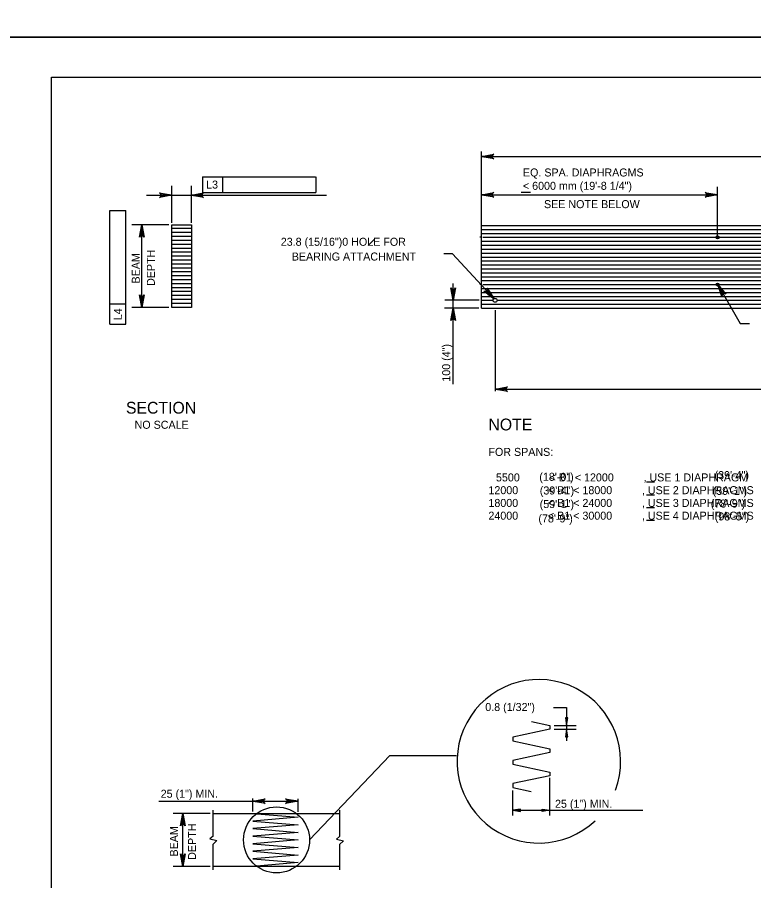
# Model space of a CAD drawing. Extents: x 638263 to 640360, y 293683 to 298655.
# Drawn here: x 639303.6 to 639579.7, y 296931.3 to 297255 of the extents above; entities that cross this region are included whole.
import ezdxf

# ---------------------------------------------------------------- set-up
doc = ezdxf.new("R2010")
doc.units = 0
for name, color, linetype in [('2', 7, 'Continuous'), ('4', 7, 'Continuous'), ('5', 7, 'Continuous'), ('6', 7, 'Continuous'), ('7', 7, 'Continuous'), ('8', 7, 'Continuous'), ('PLT-BNDY', 7, 'Continuous')]:
    doc.layers.add(name, color=color, linetype=linetype)

msp = doc.modelspace()

# ---------------------------------------------------------------- linework, layer by layer
at = {"layer": '2'}
for p, q in [((639316.46, 296668.46), (639316.46, 297232.46)), ((639316.46, 297232.46), (640102.46, 297232.46)), ((639361.52, 297146.18), (639361.52, 297177.19)), ((639361.52, 297177.19), (639368.9, 297177.19)), ((639368.9, 297177.19), (639368.9, 297146.18)), ((639477.54, 297145.89), (639477.54, 297176.89)), ((639477.54, 297176.89), (639831.87, 297176.89)), ((639368.9, 297146.18), (639361.52, 297146.18)), ((639477.54, 297145.89), (639831.87, 297145.89))]:
    msp.add_line(p, q, dxfattribs=at)
at = {"layer": '4'}
for centre, radius in [((639566.13, 297172.46), 0.554), ((639566.13, 297154.75), 0.554), ((639482.71, 297148.84), 0.738)]:
    msp.add_circle(centre, radius, dxfattribs=at)
at = {"layer": '5'}
for p, q in [((639477.54, 297177.6), (639477.54, 297204.59)), ((639477.54, 297202.73), (639831.87, 297202.73)), ((639372.96, 297195.19), (639372.96, 297189.28)), ((639372.96, 297195.19), (639380.52, 297195.19)), ((639380.52, 297195.19), (639380.52, 297189.28)), ((639380.52, 297195.19), (639415.32, 297195.19)), ((639415.48, 297195.19), (639415.48, 297189.28)), ((639361.52, 297177.92), (639361.52, 297191.75)), ((639368.9, 297177.92), (639368.9, 297191.75)), ((639477.54, 297173.02), (639477.54, 297191.37)), ((639566.12, 297173.02), (639566.12, 297191.37)), ((639352.01, 297188.26), (639419.47, 297188.26)), ((639372.96, 297189.28), (639415.48, 297189.28)), ((639477.54, 297188.4), (639566.12, 297188.4)), ((639492.44, 297189.39), (639495.95, 297189.39)), ((639338.31, 297182.46), (639344.22, 297182.46)), ((639338.31, 297147.5), (639338.31, 297182.46)), ((639344.22, 297139.94), (639344.22, 297182.46)), ((639360.4, 297177.19), (639346.58, 297177.19)), ((639350.24, 297146.18), (639350.24, 297177.19)), ((639437.51, 297171.75), (639435.11, 297169.35)), ((639484.39, 297172.46), (639857.82, 297172.46)), ((639466.7, 297166.24), (639463.51, 297166.24)), ((639482.29, 297149.45), (639466.7, 297166.24)), ((639466.95, 297117.39), (639466.95, 297155.16)), ((639484.39, 297154.75), (639872.19, 297154.75)), ((639566.14, 297154.75), (639574.58, 297140.14)), ((639476.67, 297148.84), (639463.85, 297148.84)), ((639338.31, 297139.94), (639338.31, 297147.5)), ((639338.31, 297147.5), (639344.22, 297147.5)), ((639360.4, 297146.18), (639346.58, 297146.18)), ((639476.59, 297145.89), (639463.78, 297145.89)), ((639482.71, 297145.15), (639482.71, 297114.8)), ((639338.31, 297139.94), (639344.22, 297139.94)), ((639574.58, 297140.14), (639578.07, 297140.14)), ((639482.71, 297115.54), (639826.71, 297115.54)), ((639542.51, 297080.64), (639539.41, 297080.64)), ((639542.5, 297075.85), (639539.41, 297075.85)), ((639542.5, 297071.06), (639539.4, 297071.06)), ((639542.49, 297066.31), (639539.4, 297066.31)), ((639504.62, 296996.24), (639509.51, 296996.24)), ((639509.51, 296996.24), (639509.51, 296983.76)), ((639504.9, 296989.45), (639513.11, 296989.45)), ((639504.9, 296988.03), (639513.11, 296988.03)), ((639503.2, 296955.72), (639503.2, 296969.8)), ((639489.38, 296955.72), (639489.38, 296965.14)), ((639356.59, 296961.12), (639408.84, 296961.12)), ((639391.83, 296957.25), (639391.83, 296962.09)), ((639408.84, 296957.1), (639408.84, 296962.01)), ((639376.95, 296947.94), (639376.95, 296957.74)), ((639424.43, 296957.74), (639424.43, 296947.88)), ((639489.38, 296957.65), (639538.02, 296957.65)), ((639375.83, 296956.47), (639362.02, 296956.47)), ((639365.67, 296936.63), (639365.67, 296956.47)), ((639376.95, 296947.94), (639375.81, 296946.95)), ((639424.43, 296947.88), (639423.29, 296946.89)), ((639375.81, 296946.95), (639378.41, 296946.28)), ((639378.41, 296946.28), (639376.95, 296944.93)), ((639376.95, 296935.37), (639376.95, 296944.93)), ((639423.29, 296946.89), (639425.89, 296946.22)), ((639425.89, 296946.22), (639424.43, 296944.87)), ((639424.43, 296944.87), (639424.43, 296935.37)), ((639375.83, 296936.63), (639362.02, 296936.63))]:
    msp.add_line(p, q, dxfattribs=at)
for points in [[(639477.54, 297202.73), (639482.2, 297203.6), (639481.85, 297203.35), (639481.66, 297203.04), (639481.61, 297202.73), (639481.66, 297202.42), (639481.85, 297202.1), (639482.2, 297201.86), (639477.54, 297202.73), (639481.85, 297202.1), (639481.66, 297202.42), (639477.54, 297202.73), (639481.61, 297202.73), (639481.66, 297203.04), (639477.54, 297202.73), (639481.85, 297203.35)], [(639361.52, 297188.26), (639356.86, 297187.39), (639357.22, 297187.63), (639357.4, 297187.95), (639357.46, 297188.26), (639357.4, 297188.57), (639357.22, 297188.88), (639356.86, 297189.13), (639361.52, 297188.26), (639357.22, 297188.88), (639357.4, 297188.57), (639361.52, 297188.26), (639357.46, 297188.26), (639357.4, 297187.95), (639361.52, 297188.26), (639357.22, 297187.63)], [(639368.72, 297188.26), (639373.38, 297189.13), (639373.02, 297188.88), (639372.84, 297188.57), (639372.78, 297188.26), (639372.84, 297187.95), (639373.02, 297187.63), (639373.38, 297187.39), (639368.72, 297188.26), (639373.02, 297187.63), (639372.84, 297187.95), (639368.72, 297188.26), (639372.78, 297188.26), (639372.84, 297188.57), (639368.72, 297188.26), (639373.02, 297188.88)], [(639477.54, 297188.4), (639482.2, 297189.28), (639481.85, 297189.03), (639481.66, 297188.72), (639481.61, 297188.4), (639481.66, 297188.09), (639481.85, 297187.78), (639482.2, 297187.53), (639477.54, 297188.4), (639481.85, 297187.78), (639481.66, 297188.09), (639477.54, 297188.4), (639481.61, 297188.4), (639481.66, 297188.72), (639477.54, 297188.4), (639481.85, 297189.03)], [(639566.12, 297188.4), (639561.46, 297187.53), (639561.82, 297187.78), (639562.01, 297188.09), (639562.06, 297188.4), (639562.01, 297188.72), (639561.82, 297189.03), (639561.46, 297189.28), (639566.12, 297188.4), (639561.82, 297189.03), (639562.01, 297188.72), (639566.12, 297188.4), (639562.06, 297188.4), (639562.01, 297188.09), (639566.12, 297188.4), (639561.82, 297187.78)], [(639350.24, 297177.19), (639351.11, 297172.52), (639350.86, 297172.88), (639350.55, 297173.07), (639350.24, 297173.12), (639349.93, 297173.07), (639349.61, 297172.88), (639349.37, 297172.52), (639350.24, 297177.19), (639349.61, 297172.88), (639349.93, 297173.07), (639350.24, 297177.19), (639350.24, 297173.12), (639350.55, 297173.07), (639350.24, 297177.19), (639350.86, 297172.88)], [(639466.95, 297148.84), (639466.08, 297153.5), (639466.33, 297153.14), (639466.64, 297152.96), (639466.95, 297152.9), (639467.27, 297152.96), (639467.58, 297153.14), (639467.83, 297153.5), (639466.95, 297148.84), (639467.58, 297153.14), (639467.27, 297152.96), (639466.95, 297148.84), (639466.95, 297152.9), (639466.64, 297152.96), (639466.95, 297148.84), (639466.33, 297153.14)], [(639482.29, 297149.45), (639478.48, 297152.27), (639478.91, 297152.18), (639479.26, 297152.25), (639479.53, 297152.43), (639479.72, 297152.68), (639479.82, 297153.03), (639479.76, 297153.46), (639482.29, 297149.45), (639479.82, 297153.03), (639479.72, 297152.68), (639482.29, 297149.45), (639479.53, 297152.43), (639479.26, 297152.25), (639482.29, 297149.45), (639478.91, 297152.18)], [(639566.14, 297154.75), (639569.23, 297151.15), (639568.83, 297151.34), (639568.47, 297151.34), (639568.17, 297151.23), (639567.93, 297151.03), (639567.75, 297150.71), (639567.72, 297150.27), (639566.14, 297154.75), (639567.75, 297150.71), (639567.93, 297151.03), (639566.14, 297154.75), (639568.17, 297151.23), (639568.47, 297151.34), (639566.14, 297154.75), (639568.83, 297151.34)], [(639350.24, 297146.18), (639349.37, 297150.84), (639349.61, 297150.48), (639349.93, 297150.3), (639350.24, 297150.24), (639350.55, 297150.3), (639350.86, 297150.48), (639351.11, 297150.84), (639350.24, 297146.18), (639350.86, 297150.48), (639350.55, 297150.3), (639350.24, 297146.18), (639350.24, 297150.24), (639349.93, 297150.3), (639350.24, 297146.18), (639349.61, 297150.48)], [(639466.95, 297145.89), (639467.82, 297141.23), (639467.57, 297141.59), (639467.26, 297141.77), (639466.95, 297141.83), (639466.63, 297141.77), (639466.32, 297141.59), (639466.07, 297141.23), (639466.95, 297145.89), (639466.32, 297141.59), (639466.63, 297141.77), (639466.95, 297145.89), (639466.95, 297141.83), (639467.26, 297141.77), (639466.95, 297145.89), (639467.57, 297141.59)], [(639482.71, 297115.54), (639487.37, 297116.41), (639487.01, 297116.16), (639486.83, 297115.85), (639486.77, 297115.54), (639486.83, 297115.23), (639487.01, 297114.91), (639487.37, 297114.67), (639482.71, 297115.54), (639487.01, 297114.91), (639486.83, 297115.23), (639482.71, 297115.54), (639486.77, 297115.54), (639486.83, 297115.85), (639482.71, 297115.54), (639487.01, 297116.16)], [(639391.83, 296961.12), (639396.49, 296961.99), (639396.13, 296961.75), (639395.95, 296961.43), (639395.89, 296961.12), (639395.95, 296960.81), (639396.13, 296960.5), (639396.49, 296960.25), (639391.83, 296961.12), (639396.13, 296960.5), (639395.95, 296960.81), (639391.83, 296961.12), (639395.89, 296961.12), (639395.95, 296961.43), (639391.83, 296961.12), (639396.13, 296961.75)], [(639408.84, 296961.12), (639404.18, 296960.25), (639404.54, 296960.5), (639404.72, 296960.81), (639404.78, 296961.12), (639404.72, 296961.43), (639404.54, 296961.75), (639404.18, 296961.99), (639408.84, 296961.12), (639404.54, 296961.75), (639404.72, 296961.43), (639408.84, 296961.12), (639404.78, 296961.12), (639404.72, 296960.81), (639408.84, 296961.12), (639404.54, 296960.5)], [(639365.67, 296956.47), (639366.54, 296951.81), (639366.29, 296952.17), (639365.98, 296952.36), (639365.67, 296952.41), (639365.36, 296952.36), (639365.04, 296952.17), (639364.8, 296951.81), (639365.67, 296956.47), (639365.04, 296952.17), (639365.36, 296952.36), (639365.67, 296956.47), (639365.67, 296952.41), (639365.98, 296952.36), (639365.67, 296956.47), (639366.29, 296952.17)], [(639365.67, 296936.63), (639364.8, 296941.29), (639365.04, 296940.93), (639365.36, 296940.75), (639365.67, 296940.69), (639365.98, 296940.75), (639366.29, 296940.93), (639366.54, 296941.29), (639365.67, 296936.63), (639366.29, 296940.93), (639365.98, 296940.75), (639365.67, 296936.63), (639365.67, 296940.69), (639365.36, 296940.75), (639365.67, 296936.63), (639365.04, 296940.93)]]:
    msp.add_lwpolyline(points, dxfattribs=at)
for points in [[(639480.71, 297151.85), (639480.02, 297151.21), (639482.29, 297149.45)], [(639509.98, 296992.29), (639509.03, 296992.29), (639509.51, 296989.45)], [(639509.03, 296985.2), (639509.98, 296985.2), (639509.51, 296988.03)], [(639492.22, 296957.18), (639492.22, 296958.13), (639489.38, 296957.65)], [(639500.37, 296957.18), (639500.37, 296958.13), (639503.2, 296957.65)]]:
    msp.add_lwpolyline(points, close=True, dxfattribs=at)
at = {"layer": '6'}
for p, q in [((639368.9, 297175.71), (639361.52, 297175.71)), ((639368.9, 297174.23), (639361.52, 297174.23)), ((639477.54, 297175.42), (639831.87, 297175.42)), ((639368.9, 297172.76), (639361.52, 297172.76)), ((639368.9, 297171.28), (639361.52, 297171.28)), ((639477.54, 297172.46), (639476.99, 297172.46)), ((639477.54, 297173.94), (639831.87, 297173.94)), ((639477.54, 297170.99), (639831.87, 297170.99)), ((639478.1, 297172.46), (639565.57, 297172.46)), ((639566.68, 297172.46), (639654.15, 297172.46)), ((639368.9, 297169.8), (639361.52, 297169.8)), ((639368.9, 297168.33), (639361.52, 297168.33)), ((639477.54, 297169.51), (639831.87, 297169.51)), ((639477.54, 297168.04), (639831.87, 297168.04)), ((639368.9, 297166.85), (639361.52, 297166.85)), ((639368.9, 297165.37), (639361.52, 297165.37)), ((639477.54, 297166.56), (639831.87, 297166.56)), ((639477.54, 297165.08), (639831.87, 297165.08)), ((639368.9, 297163.9), (639361.52, 297163.9)), ((639368.9, 297162.42), (639361.52, 297162.42)), ((639477.54, 297163.61), (639831.87, 297163.61)), ((639477.54, 297162.13), (639831.87, 297162.13)), ((639368.9, 297160.94), (639361.52, 297160.94)), ((639368.9, 297159.47), (639361.52, 297159.47)), ((639477.54, 297160.65), (639831.87, 297160.65)), ((639477.54, 297159.18), (639831.87, 297159.18)), ((639368.9, 297157.99), (639361.52, 297157.99)), ((639368.9, 297156.51), (639361.52, 297156.51)), ((639368.9, 297155.04), (639361.52, 297155.04)), ((639477.54, 297157.7), (639831.87, 297157.7)), ((639477.54, 297156.22), (639831.87, 297156.22)), ((639368.9, 297153.56), (639361.52, 297153.56)), ((639368.9, 297152.09), (639361.52, 297152.09)), ((639477.54, 297154.75), (639476.99, 297154.75)), ((639477.54, 297153.27), (639831.87, 297153.27)), ((639477.54, 297151.79), (639831.87, 297151.79)), ((639478.1, 297154.75), (639565.57, 297154.75)), ((639566.68, 297154.75), (639654.15, 297154.75)), ((639368.9, 297150.61), (639361.52, 297150.61)), ((639368.9, 297149.13), (639361.52, 297149.13)), ((639477.54, 297150.32), (639831.87, 297150.32)), ((639477.54, 297148.84), (639481.97, 297148.84)), ((639483.45, 297148.84), (639825.97, 297148.84)), ((639368.9, 297147.66), (639361.52, 297147.66)), ((639477.54, 297147.36), (639831.87, 297147.36))]:
    msp.add_line(p, q, dxfattribs=at)
at = {"layer": '7'}
for p, q in [((639496.29, 296990.92), (639503.2, 296989.45)), ((639503.2, 296988.03), (639489.38, 296985.1)), ((639503.2, 296989.45), (639503.2, 296988.03)), ((639489.38, 296985.1), (639489.38, 296983.68)), ((639489.38, 296983.68), (639503.2, 296980.74)), ((639503.2, 296980.74), (639503.2, 296979.33)), ((639503.2, 296979.33), (639489.34, 296976.38)), ((639489.34, 296976.38), (639489.34, 296974.96)), ((639489.34, 296974.96), (639503.2, 296972.01)), ((639503.2, 296970.6), (639489.34, 296967.65)), ((639503.2, 296972.01), (639503.2, 296970.6)), ((639489.34, 296967.65), (639489.34, 296966.23)), ((639489.34, 296966.23), (639496.27, 296964.76)), ((639376.95, 296956.47), (639424.43, 296956.47)), ((639391.83, 296956.47), (639408.84, 296955.06)), ((639408.84, 296955.06), (639391.83, 296953.64)), ((639391.83, 296953.64), (639408.84, 296952.22)), ((639408.84, 296952.22), (639391.83, 296950.8)), ((639391.83, 296950.8), (639408.84, 296949.39)), ((639408.84, 296949.39), (639391.83, 296947.97)), ((639391.83, 296947.97), (639408.84, 296946.55)), ((639408.84, 296946.55), (639391.83, 296945.13)), ((639391.83, 296945.13), (639408.84, 296943.72)), ((639408.84, 296943.72), (639391.83, 296942.3)), ((639391.83, 296942.3), (639408.84, 296940.88)), ((639408.84, 296940.88), (639391.83, 296939.47)), ((639391.83, 296939.47), (639408.84, 296938.05)), ((639408.84, 296938.05), (639391.83, 296936.63)), ((639424.43, 296936.63), (639376.95, 296936.63))]:
    msp.add_line(p, q, dxfattribs=at)
at = {"layer": '8'}
for p, q in [((639413.15, 296946.55), (639443.3, 296978.17)), ((639443.3, 296978.17), (639468.22, 296978.17))]:
    msp.add_line(p, q, dxfattribs=at)
msp.add_circle((639400.78, 296946.55), 12.37, dxfattribs=at)
msp.add_arc((639499.09, 296976.03), 30.66, 339.3834, 313.4181, dxfattribs=at)
at = {"layer": 'PLT-BNDY'}
for points in [[(639276.46, 297841.46), (640117.46, 297841.46), (640117.46, 297247.46), (639276.46, 297247.46)], [(639276.46, 297247.46), (640117.46, 297247.46), (640117.46, 296653.46), (639276.46, 296653.46)]]:
    msp.add_lwpolyline(points, close=True, dxfattribs=at)

# ---------------------------------------------------------------- texts
at = {"layer": '2'}
for s, p in [('(18\'-0")', (639499.28, 297081.18)), ('(39\'-4")', (639564.98, 297081.82)), ('(39\'-4")', (639499.45, 297076.06)), ('(59\'-1")', (639564.29, 297075.9)), ('(59\'-1")', (639499.42, 297070.97)), ('(78\'-9")', (639563.55, 297071.16)), ('(78\'-9")', (639498.94, 297065.58)), ('(98\'-5")', (639565.05, 297066.32))]:
    msp.add_text(s, height=3, dxfattribs=at).set_placement(p)
at = {"layer": '5'}
for s, height, p in [('EQ. SPA. DIAPHRAGMS', 3, (639493.13, 297195.27)), ('< 6000 mm (19\'-8 1/4")', 3, (639493.13, 297190.27)), ('SEE NOTE BELOW', 3, (639501.03, 297183.4)), ('23.8 (15/16")0 HOLE FOR', 3, (639402.35, 297169.29)), ('BEARING ATTACHMENT', 3, (639406.49, 297163.76)), ('SECTION', 4.429, (639344.31, 297106.36)), ('NO SCALE', 3, (639347.56, 297100.69)), ('NOTE', 4.429, (639480.2, 297100.08)), ('FOR SPANS:', 3, (639480.2, 297090.52)), ('5500          < B1 < 12000          , USE 1 DIAPHRAGM', 3, (639483.03, 297080.96)), ('12000          < B1 < 18000          , USE 2 DIAPHRAGMS', 3, (639480.2, 297076.17)), ('18000          < B1 < 24000          , USE 3 DIAPHRAGMS', 3, (639480.2, 297071.39)), ('24000          < B1 < 30000          , USE 4 DIAPHRAGMS', 3, (639480.2, 297066.61)), ('0.8 (1/32")', 3, (639479.02, 296994.88)), ('25 (1") MIN.', 3, (639357.34, 296962.37)), ('25 (1") MIN.', 3, (639505.16, 296958.61))]:
    msp.add_text(s, height=height, dxfattribs=at).set_placement(p)
for s, rotation, p in [('L3', 359.9382, (639374.37, 297190.74)), ('BEAM', 90, (639349.5, 297155.16)), ('DEPTH', 90, (639355.15, 297154.24)), ('L4', 89.9382, (639342.77, 297141.36)), ('100 (4")', 90, (639465.86, 297118.35)), ('BEAM', 90, (639363.8, 296940.34)), ('DEPTH', 90, (639370.58, 296939.08))]:
    msp.add_text(s, height=3, rotation=rotation, dxfattribs=at).set_placement(p)

doc.saveas('drawing.dxf')
